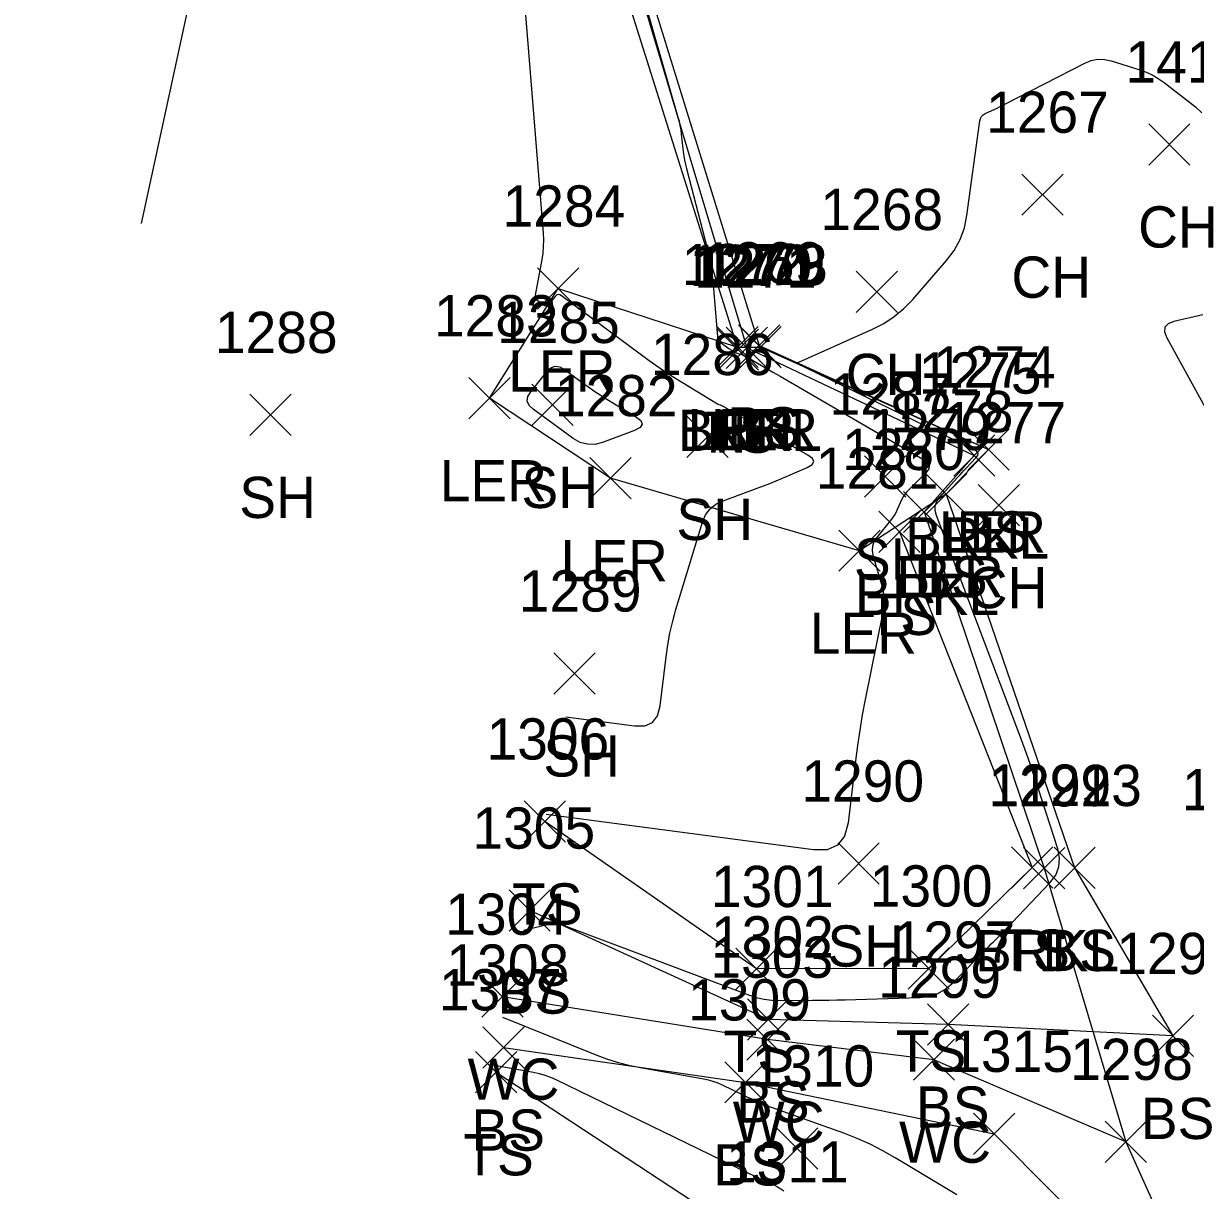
# Model space of a CAD drawing. Extents: x 1592612 to 1596497, y 111838 to 113741.
# Drawn here: x 1592866.6 to 1592923.4, y 113275.4 to 113332 of the extents above; entities that cross this region are included whole.
import ezdxf

# ---------------------------------------------------------------- set-up
doc = ezdxf.new("R2010")
doc.units = 0
for name, color, linetype in [('L_A', 7, 'Continuous'), ('L_I', 7, 'Continuous'), ('L_TIC', 7, 'Continuous'), ('LARO', 7, 'Continuous'), ('LAWE', 7, 'Continuous'), ('LELB', 7, 'Continuous'), ('LSOGCMA', 7, 'Continuous'), ('LSOGCMI', 7, 'Continuous')]:
    doc.layers.add(name, color=color, linetype=linetype)

msp = doc.modelspace()

# ---------------------------------------------------------------- linework, layer by layer
at = {"layer": 'L_TIC'}
for points in [[(1592921.135, 113325.171), (1592923.135, 113327.171)], [(1592923.135, 113325.171), (1592921.135, 113327.171)], [(1592914.993, 113322.736), (1592916.993, 113324.736)], [(1592916.993, 113322.736), (1592914.993, 113324.736)], [(1592891.508, 113318.186), (1592893.508, 113320.186)], [(1592893.508, 113318.186), (1592891.508, 113320.186)], [(1592906.96, 113318.019), (1592908.96, 113320.019)], [(1592908.96, 113318.019), (1592906.96, 113320.019)], [(1592900.199, 113315.348), (1592902.199, 113317.348)], [(1592902.199, 113315.348), (1592900.199, 113317.348)], [(1592900.227, 113315.219), (1592902.227, 113317.219)], [(1592902.227, 113315.219), (1592900.227, 113317.219)], [(1592900.227, 113315.219), (1592902.227, 113317.219)], [(1592902.227, 113315.219), (1592900.227, 113317.219)], [(1592900.657, 113315.308), (1592902.657, 113317.308)], [(1592902.657, 113315.308), (1592900.657, 113317.308)], [(1592901.257, 113315.43), (1592903.257, 113317.43)], [(1592903.257, 113315.43), (1592901.257, 113317.43)], [(1592901.321, 113315.343), (1592903.321, 113317.343)], [(1592903.321, 113315.343), (1592901.321, 113317.343)], [(1592888.183, 113312.864), (1592890.183, 113314.864)], [(1592890.183, 113312.864), (1592888.183, 113314.864)], [(1592891.242, 113312.542), (1592893.242, 113314.542)], [(1592893.242, 113312.542), (1592891.242, 113314.542)], [(1592877.563, 113312.058), (1592879.563, 113314.058)], [(1592879.563, 113312.058), (1592877.563, 113314.058)], [(1592898.754, 113310.989), (1592900.754, 113312.989)], [(1592900.754, 113310.989), (1592898.754, 113312.989)], [(1592911.684, 113310.087), (1592913.684, 113312.087)], [(1592913.684, 113310.087), (1592911.684, 113312.087)], [(1592912.374, 113310.382), (1592914.374, 113312.382)], [(1592914.374, 113310.382), (1592912.374, 113312.382)], [(1592912.374, 113310.382), (1592914.374, 113312.382)], [(1592914.374, 113310.382), (1592912.374, 113312.382)], [(1592894.043, 113308.992), (1592896.043, 113310.992)], [(1592896.043, 113308.992), (1592894.043, 113310.992)], [(1592907.359, 113309.066), (1592909.359, 113311.066)], [(1592909.359, 113309.066), (1592907.359, 113311.066)], [(1592910.324, 113308.219), (1592912.324, 113310.219)], [(1592912.324, 113308.219), (1592910.324, 113310.219)], [(1592910.324, 113308.219), (1592912.324, 113310.219)], [(1592912.324, 113308.219), (1592910.324, 113310.219)], [(1592912.876, 113307.682), (1592914.876, 113309.682)], [(1592914.876, 113307.682), (1592912.876, 113309.682)], [(1592909.248, 113307.35), (1592911.248, 113309.35)], [(1592911.248, 113307.35), (1592909.248, 113309.35)], [(1592908.051, 113306.385), (1592910.051, 113308.385)], [(1592910.051, 113306.385), (1592908.051, 113308.385)], [(1592906.122, 113305.473), (1592908.122, 113307.473)], [(1592908.122, 113305.473), (1592906.122, 113307.473)], [(1592892.303, 113299.523), (1592894.303, 113301.523)], [(1592894.303, 113299.523), (1592892.303, 113301.523)], [(1592890.864, 113292.346), (1592892.864, 113294.346)], [(1592892.864, 113292.346), (1592890.864, 113294.346)], [(1592906.078, 113290.307), (1592908.078, 113292.307)], [(1592908.078, 113290.307), (1592906.078, 113292.307)], [(1592914.488, 113290.108), (1592916.488, 113292.108)], [(1592916.488, 113290.108), (1592914.488, 113292.108)], [(1592915.07, 113290.076), (1592917.07, 113292.076)], [(1592917.07, 113290.076), (1592915.07, 113292.076)], [(1592916.546, 113290.093), (1592918.546, 113292.093)], [(1592918.546, 113290.093), (1592916.546, 113292.093)], [(1592890.129, 113288.026), (1592892.129, 113290.026)], [(1592892.129, 113288.026), (1592890.129, 113290.026)], [(1592901.12, 113285.194), (1592903.12, 113287.194)], [(1592903.12, 113285.194), (1592901.12, 113287.194)], [(1592909.471, 113285.219), (1592911.471, 113287.219)], [(1592911.471, 113285.219), (1592909.471, 113287.219)], [(1592888.809, 113283.85), (1592890.809, 113285.85)], [(1592890.809, 113283.85), (1592888.809, 113285.85)], [(1592901.691, 113282.749), (1592903.691, 113284.749)], [(1592903.691, 113282.749), (1592901.691, 113284.749)], [(1592910.412, 113282.497), (1592912.412, 113284.497)], [(1592912.412, 113282.497), (1592910.412, 113284.497)], [(1592901.664, 113281.767), (1592903.664, 113283.767)], [(1592903.664, 113281.767), (1592901.664, 113283.767)], [(1592921.313, 113281.948), (1592923.313, 113283.948)], [(1592923.313, 113281.948), (1592921.313, 113283.948)], [(1592888.863, 113281.382), (1592890.863, 113283.382)], [(1592890.863, 113281.382), (1592888.863, 113283.382)], [(1592909.728, 113280.795), (1592911.728, 113282.795)], [(1592911.728, 113280.795), (1592909.728, 113282.795)], [(1592888.501, 113280.185), (1592890.501, 113282.185)], [(1592890.501, 113280.185), (1592888.501, 113282.185)], [(1592900.59, 113279.696), (1592902.59, 113281.696)], [(1592902.59, 113279.696), (1592900.59, 113281.696)], [(1592912.642, 113277.201), (1592914.642, 113279.201)], [(1592914.642, 113277.201), (1592912.642, 113279.201)], [(1592903.097, 113276.491), (1592905.097, 113278.491)], [(1592905.097, 113276.491), (1592903.097, 113278.491)], [(1592919.024, 113276.813), (1592921.024, 113278.813)], [(1592921.024, 113276.813), (1592919.024, 113278.813)], [(1592919.024, 113276.813), (1592921.024, 113278.813)], [(1592921.024, 113276.813), (1592919.024, 113278.813)]]:
    msp.add_lwpolyline(points, dxfattribs=at)
at = {"layer": 'LARO'}
for points in [[(1592901.199, 113316.348), (1592902.321, 113316.343), (1592913.374, 113311.383), (1592911.324, 113309.219), (1592907.122, 113306.473), (1592895.043, 113309.992), (1592889.183, 113313.864), (1592892.508, 113319.186)], [(1592907.122, 113306.473), (1592895.043, 113309.992), (1592889.183, 113313.864), (1592892.508, 113319.186)], [(1592892.508, 113319.186), (1592901.199, 113316.348)], [(1592901.199, 113316.348), (1592902.321, 113316.343), (1592913.374, 113311.382), (1592911.324, 113309.219), (1592907.122, 113306.473)]]:
    msp.add_lwpolyline(points, dxfattribs=at)
at = {"layer": 'LAWE'}
for points in [[(1592867.923, 113458.263), (1592869.843, 113440.453), (1592871.967, 113422.356), (1592872.93, 113405.001), (1592883.346, 113373.9), (1592893.179, 113344.656), (1592901.657, 113316.308), (1592912.684, 113311.087), (1592910.248, 113308.35), (1592916.07, 113291.076)], [(1592916.07, 113291.076), (1592920.024, 113277.813), (1592925.099, 113266.526)], [(1592920.024, 113277.814), (1592910.728, 113281.795), (1592902.664, 113282.767), (1592889.809, 113284.85)]]:
    msp.add_lwpolyline(points, dxfattribs=at)
at = {"layer": 'LELB'}
for points in [[(1592866.59, 113458.717), (1592868.12, 113440.226), (1592870.678, 113422.668), (1592871.235, 113404.668), (1592883.079, 113373.124), (1592885.764, 113364.063), (1592892.434, 113344.134), (1592901.184, 113316.355)], [(1592873.192, 113458.509), (1592876.893, 113440.279), (1592874.766, 113422.722), (1592874.598, 113405.543), (1592883.851, 113374.09), (1592893.431, 113344.94), (1592902.258, 113316.43), (1592913.374, 113311.383), (1592911.324, 113309.219), (1592917.546, 113291.093), (1592922.314, 113282.948), (1592911.412, 113283.497), (1592902.691, 113283.749), (1592891.129, 113289.026)], [(1592909.052, 113307.385), (1592915.488, 113291.108), (1592910.471, 113286.219), (1592902.12, 113286.193), (1592891.864, 113293.346)], [(1592889.863, 113282.382), (1592901.59, 113280.696), (1592913.642, 113278.201), (1592924.996, 113266.796), (1592943.132, 113254.464), (1592958.132, 113248.138), (1592963.265, 113252.408), (1592986.408, 113242.634)], [(1592889.501, 113281.185), (1592902.204, 113272.845), (1592904.97, 113262.973), (1592917.653, 113259.488), (1592925.476, 113266.102)]]:
    msp.add_lwpolyline(points, dxfattribs=at)
at = {"layer": 'LSOGCMA'}
for points in [[(1592895.548, 113337.127), (1592898.314, 113327.501), (1592898.369, 113327.296), (1592898.414, 113327.09), (1592898.451, 113326.882), (1592898.479, 113326.673), (1592898.575, 113325.831), (1592898.603, 113325.621), (1592898.638, 113325.412), (1592898.68, 113325.205), (1592898.729, 113324.999), (1592899.728, 113321.135), (1592899.831, 113320.696), (1592899.916, 113320.254), (1592899.982, 113319.809), (1592900.029, 113319.36), (1592900.253, 113316.668), (1592900.254, 113316.663), (1592900.256, 113316.66), (1592900.259, 113316.657), (1592900.263, 113316.655), (1592900.281, 113316.648), (1592900.285, 113316.646), (1592900.289, 113316.644), (1592900.294, 113316.642), (1592900.297, 113316.639), (1592900.778, 113316.282), (1592900.809, 113316.259), (1592900.841, 113316.237), (1592900.874, 113316.216), (1592900.907, 113316.195), (1592901.041, 113316.114), (1592901.075, 113316.095), (1592901.11, 113316.078), (1592901.146, 113316.063), (1592901.182, 113316.05), (1592901.402, 113315.981), (1592901.45, 113315.964), (1592901.498, 113315.945), (1592901.544, 113315.923), (1592901.589, 113315.899), (1592902.56, 113315.341), (1592902.737, 113315.239), (1592902.914, 113315.137), (1592903.09, 113315.035), (1592903.267, 113314.932), (1592910.267, 113310.867), (1592910.433, 113310.736), (1592910.501, 113310.593), (1592910.471, 113310.437), (1592910.345, 113310.268), (1592909.486, 113309.415), (1592909.393, 113309.314), (1592909.311, 113309.206), (1592909.239, 113309.091), (1592909.177, 113308.968), (1592908.951, 113308.465), (1592908.89, 113308.341), (1592908.823, 113308.222), (1592908.747, 113308.108), (1592908.665, 113307.998), (1592907.935, 113307.09), (1592907.812, 113306.897), (1592907.744, 113306.693), (1592907.729, 113306.479), (1592907.77, 113306.254), (1592908.198, 113304.793), (1592908.272, 113304.471), (1592908.306, 113304.148), (1592908.3, 113303.824), (1592908.254, 113303.497), (1592907.397, 113299.262), (1592907.254, 113298.52), (1592907.127, 113297.775), (1592907.016, 113297.027), (1592906.919, 113296.277), (1592906.563, 113293.273), (1592906.392, 113292.628), (1592906.055, 113292.196), (1592905.553, 113291.976), (1592904.886, 113291.969), (1592891.933, 113293.687)], [(1592889.594, 113281.493), (1592891.308, 113281.19), (1592891.59, 113281.13), (1592891.866, 113281.05), (1592892.136, 113280.952), (1592892.4, 113280.835), (1592901.602, 113276.364), (1592901.772, 113276.281), (1592901.942, 113276.2), (1592902.113, 113276.119), (1592902.284, 113276.039), (1592902.968, 113275.72), (1592903.136, 113275.635), (1592903.297, 113275.539), (1592903.452, 113275.434)]]:
    msp.add_lwpolyline(points, dxfattribs=at)
at = {"layer": 'LSOGCMI'}
for points in [[(1592885.13, 113362.836), (1592883.145, 113354.876), (1592882.951, 113354.227), (1592882.699, 113353.604), (1592882.391, 113353.007), (1592882.025, 113352.437), (1592880.017, 113349.605), (1592879.829, 113349.357), (1592879.627, 113349.123), (1592879.41, 113348.902), (1592879.179, 113348.695), (1592878.224, 113347.893), (1592878.007, 113347.679), (1592877.833, 113347.44), (1592877.702, 113347.174), (1592877.614, 113346.882), (1592872.292, 113322.344)], [(1592892.881, 113298.421), (1592896.215, 113297.979), (1592896.709, 113297.984), (1592897.081, 113298.146), (1592897.331, 113298.467), (1592897.458, 113298.944), (1592897.74, 113301.327), (1592897.821, 113301.907), (1592897.929, 113302.482), (1592898.061, 113303.051), (1592898.219, 113303.615), (1592899.506, 113307.85), (1592899.657, 113308.205), (1592899.873, 113308.498), (1592900.154, 113308.729), (1592900.501, 113308.898), (1592902.162, 113309.5), (1592902.47, 113309.614), (1592902.776, 113309.734), (1592903.081, 113309.858), (1592903.383, 113309.987), (1592904.588, 113310.512), (1592904.816, 113310.647), (1592904.897, 113310.791), (1592904.832, 113310.942), (1592904.621, 113311.102), (1592900.46, 113313.493), (1592900.443, 113313.503), (1592900.425, 113313.511), (1592900.407, 113313.519), (1592900.388, 113313.525), (1592900.313, 113313.549), (1592900.294, 113313.555), (1592900.276, 113313.563), (1592900.258, 113313.571), (1592900.241, 113313.581), (1592898.239, 113314.796), (1592897.902, 113315.006), (1592897.57, 113315.223), (1592897.244, 113315.449), (1592896.923, 113315.682), (1592892.677, 113318.837), (1592892.59, 113318.884), (1592892.507, 113318.893), (1592892.43, 113318.864), (1592892.357, 113318.796), (1592892.045, 113318.407), (1592891.989, 113318.354), (1592891.929, 113318.332), (1592891.865, 113318.339), (1592891.798, 113318.376), (1592891.521, 113318.587), (1592891.463, 113318.643), (1592891.426, 113318.708), (1592891.409, 113318.781), (1592891.414, 113318.862), (1592891.73, 113320.59), (1592891.777, 113320.906), (1592891.804, 113321.224), (1592891.809, 113321.543), (1592891.794, 113321.863), (1592890.029, 113343.855)], [(1592890.826, 113288.068), (1592891.994, 113288.357), (1592892.188, 113288.39), (1592892.38, 113288.394), (1592892.57, 113288.368), (1592892.759, 113288.312), (1592901.741, 113284.935), (1592902.113, 113284.814), (1592902.491, 113284.729), (1592902.876, 113284.679), (1592903.266, 113284.664), (1592904.842, 113284.676), (1592905.236, 113284.68), (1592905.63, 113284.686), (1592906.024, 113284.695), (1592906.418, 113284.705), (1592910.043, 113284.811), (1592910.479, 113284.863), (1592910.882, 113284.992), (1592911.251, 113285.197), (1592911.588, 113285.48), (1592913.3, 113287.199), (1592913.403, 113287.302), (1592913.505, 113287.406), (1592913.608, 113287.509), (1592913.71, 113287.613), (1592914.119, 113288.027), (1592914.221, 113288.131), (1592914.323, 113288.236), (1592914.424, 113288.341), (1592914.524, 113288.446), (1592916.351, 113290.374), (1592916.628, 113290.744), (1592916.783, 113291.142), (1592916.816, 113291.568), (1592916.727, 113292.022), (1592915.8, 113294.912), (1592915.592, 113295.548), (1592915.375, 113296.181), (1592915.15, 113296.811), (1592914.917, 113297.439), (1592910.844, 113308.185), (1592910.784, 113308.426), (1592910.792, 113308.654), (1592910.868, 113308.87), (1592911.011, 113309.072), (1592911.851, 113310.002), (1592911.963, 113310.126), (1592912.076, 113310.249), (1592912.19, 113310.371), (1592912.304, 113310.492), (1592912.764, 113310.977), (1592912.846, 113311.093), (1592912.862, 113311.196), (1592912.811, 113311.287), (1592912.694, 113311.366), (1592903.919, 113315.624), (1592903.897, 113315.635), (1592903.89, 113315.641), (1592903.899, 113315.641), (1592903.924, 113315.636), (1592904.054, 113315.602), (1592904.086, 113315.596), (1592904.118, 113315.596), (1592904.149, 113315.601), (1592904.18, 113315.612), (1592907.743, 113317.207), (1592908.293, 113317.489), (1592908.803, 113317.825), (1592909.273, 113318.215), (1592909.702, 113318.659), (1592911.341, 113320.544), (1592911.71, 113321.033), (1592911.997, 113321.559), (1592912.204, 113322.123), (1592912.328, 113322.723), (1592912.953, 113327.319), (1592912.982, 113327.434), (1592913.036, 113327.532), (1592913.113, 113327.611), (1592913.216, 113327.672), (1592913.673, 113327.881), (1592913.787, 113327.934), (1592913.9, 113327.988), (1592914.013, 113328.043), (1592914.125, 113328.1), (1592918.036, 113330.115), (1592918.349, 113330.242), (1592918.668, 113330.302), (1592918.994, 113330.297), (1592919.324, 113330.226), (1592920.659, 113329.808), (1592920.985, 113329.69), (1592921.297, 113329.545), (1592921.595, 113329.372), (1592921.879, 113329.172), (1592923.404, 113327.993), (1592923.709, 113327.704)], [(1592923.762, 113317.902), (1592922.361, 113317.584), (1592922.076, 113317.475), (1592921.922, 113317.307), (1592921.899, 113317.081), (1592922.008, 113316.796), (1592924.397, 113312.472)], [(1592911.837, 113275.242), (1592908.854, 113277.038), (1592908.25, 113277.382), (1592907.632, 113277.694), (1592906.999, 113277.976), (1592906.351, 113278.226), (1592902.621, 113279.563), (1592902.521, 113279.6), (1592902.421, 113279.64), (1592902.323, 113279.682), (1592902.226, 113279.726), (1592901.838, 113279.907), (1592901.741, 113279.952), (1592901.645, 113279.998), (1592901.548, 113280.044), (1592901.452, 113280.091), (1592900.471, 113280.567), (1592900.274, 113280.655), (1592900.071, 113280.729), (1592899.864, 113280.788), (1592899.652, 113280.833), (1592896.581, 113281.377), (1592896.002, 113281.495), (1592895.431, 113281.643), (1592894.869, 113281.821), (1592894.316, 113282.028), (1592889.831, 113283.841)]]:
    msp.add_lwpolyline(points, dxfattribs=at)
msp.add_lwpolyline([(1592891.098, 113313.521), (1592891.014, 113313.724), (1592891.041, 113313.943), (1592891.179, 113314.177), (1592891.962, 113315.151), (1592892.158, 113315.335), (1592892.367, 113315.414), (1592892.589, 113315.39), (1592892.825, 113315.262), (1592893.795, 113314.541), (1592894.039, 113314.364), (1592894.288, 113314.192), (1592894.54, 113314.027), (1592894.796, 113313.867), (1592896.266, 113312.975), (1592896.51, 113312.783), (1592896.581, 113312.606), (1592896.479, 113312.446), (1592896.203, 113312.302), (1592894.656, 113311.725), (1592894.284, 113311.63), (1592893.925, 113311.631), (1592893.578, 113311.726), (1592893.245, 113311.916), (1592891.293, 113313.332)], close=True, dxfattribs=at)

# ---------------------------------------------------------------- texts
at = {"layer": 'L_A'}
for s, p in [('CH', (1592920.624, 113321.171)), ('CH', (1592914.481, 113318.736)), ('LER', (1592890.09, 113314.186)), ('CH', (1592906.448, 113314.019)), ('BRKL', (1592898.303, 113311.308)), ('LER', (1592898.782, 113311.348)), ('TS', (1592899.636, 113311.219)), ('NF', (1592899.707, 113311.219)), ('LER', (1592899.904, 113311.343)), ('BS', (1592900.698, 113311.43)), ('LER', (1592886.766, 113308.864)), ('SH', (1592890.73, 113308.542)), ('SH', (1592877.051, 113308.058)), ('SH', (1592898.243, 113306.989)), ('BRKL', (1592909.329, 113306.087)), ('LER', (1592910.957, 113306.382)), ('BS', (1592911.815, 113306.382)), ('LER', (1592892.625, 113304.992)), ('SH', (1592906.847, 113305.066)), ('LER', (1592908.907, 113304.219)), ('BS', (1592909.765, 113304.219)), ('CH', (1592912.364, 113303.682)), ('BRKL', (1592906.894, 113303.35)), ('TS', (1592907.461, 113302.385)), ('LER', (1592904.705, 113301.473)), ('SH', (1592891.791, 113295.523)), ('TS', (1592890.274, 113288.346)), ('SH', (1592905.566, 113286.307)), ('BRKL', (1592912.716, 113286.076)), ('TS', (1592913.898, 113286.108)), ('BS', (1592915.986, 113286.093)), ('BS', (1592889.57, 113284.026)), ('TS', (1592900.529, 113281.194)), ('TS', (1592908.88, 113281.219)), ('WC', (1592888.116, 113279.85)), ('BS', (1592901.132, 113278.749)), ('BS', (1592909.853, 113278.497)), ('WC', (1592900.971, 113277.767)), ('BS', (1592920.754, 113277.948)), ('BS', (1592888.304, 113277.382)), ('WC', (1592909.035, 113276.795)), ('TS', (1592887.911, 113276.185)), ('BS', (1592900.03, 113275.696))]:
    msp.add_text(s, height=2, dxfattribs=at).set_placement(p)
at = {"layer": 'L_I'}
for s, p in [('1415', (1592920.009, 113329.171)), ('1267', (1592913.253, 113326.736)), ('1284', (1592889.815, 113322.186)), ('1268', (1592905.22, 113322.019)), ('1272', (1592898.506, 113319.348)), ('1270', (1592898.878, 113319.308)), ('1271', (1592899.101, 113319.219)), ('1271', (1592899.101, 113319.219)), ('1269', (1592899.509, 113319.43)), ('1273', (1592899.628, 113319.343)), ('1283', (1592886.49, 113316.864)), ('1285', (1592889.549, 113316.542)), ('1288', (1592875.87, 113316.058)), ('1286', (1592897.006, 113314.989)), ('1274', (1592910.681, 113314.382)), ('1274', (1592910.681, 113314.382)), ('1275', (1592909.991, 113314.087)), ('1282', (1592892.35, 113312.992)), ('1287', (1592905.666, 113313.066)), ('1278', (1592908.631, 113312.219)), ('1278', (1592908.631, 113312.219)), ('1277', (1592911.183, 113311.682)), ('1279', (1592907.547, 113311.35)), ('1280', (1592906.272, 113310.385)), ('1281', (1592904.996, 113309.473)), ('1289', (1592890.602, 113303.523)), ('1306', (1592889.038, 113296.346)), ('1290', (1592904.298, 113294.307)), ('1291', (1592913.362, 113294.108)), ('1292', (1592913.377, 113294.076)), ('1293', (1592914.853, 113294.093)), ('1294', (1592922.744, 113293.892)), ('1305', (1592888.357, 113292.026)), ('1301', (1592899.915, 113289.194)), ('1300', (1592907.613, 113289.219)), ('1304', (1592887.037, 113287.85)), ('1302', (1592899.919, 113286.749)), ('1297', (1592908.719, 113286.497)), ('1303', (1592899.892, 113285.767)), ('1296', (1592919.565, 113285.948)), ('1308', (1592887.091, 113285.382)), ('1299', (1592908.027, 113284.795)), ('1307', (1592886.73, 113284.185)), ('1309', (1592898.81, 113283.696)), ('1315', (1592911.516, 113281.201)), ('1310', (1592901.884, 113280.491)), ('1298', (1592917.331, 113280.813)), ('1298', (1592917.331, 113280.813)), ('1311', (1592900.645, 113275.844))]:
    msp.add_text(s, height=2, dxfattribs=at).set_placement(p)

doc.saveas('drawing.dxf')
